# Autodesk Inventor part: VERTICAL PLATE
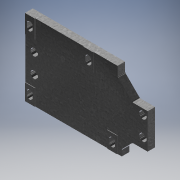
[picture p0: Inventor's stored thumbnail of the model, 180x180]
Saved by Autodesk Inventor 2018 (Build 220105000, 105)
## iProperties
Created: 2004-06
Part Number: VERTICAL PLATE
Document SubType Name: Modeling
Manufacturer: Standard
Standards Organization: Custom
Material: Steel, Mild
Density: 7.86 g/cm^3
Mass: 3865.22 g
Surface Area: 833.818 cm^2
Volume: 491.758 cm^3
Appearance: Steel Galvanized
Author: Autodesk, Inc.
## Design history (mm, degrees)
sketch "Sketch1"
  geometry: L1 (-123.35, 77)-(123.35, 77); L2 (123.35, 77)-(123.35, -77); L3 (123.35, -77)-(-123.35, -77); L4 (-123.35, -77)-(-123.35, 77); 3 further points
  constraints: 8 end point, 2 midpoint, 2 parallel, 1 horizontal, 1 horizontal alignment, 1 perpendicular, 1 vertical alignment
  dimensions: "d0" = 246.7 distance of L1.start L1.end; "d1" = 154 distance of L1.end L2.end
extrude "Extrusion1" new body sketch "Sketch1" distance "d2" = 15; taper "d3" = 0 deg
sketch "Sketch2"
  geometry: L1 (-123.35, 77)-(123.35, 77) reference; L2 (123.35, 77)-(123.35, -77) reference; L3 (62.65, 77)-(62.65, 28.2); L4 (62.65, 28.2)-(123.35, 28.2); L5 (123.35, -77)-(-123.35, -77) reference; L6 (62.65, 58.2)-(92.65, 28.2)
  constraints: 6 end point, 4 point on line, 2 perpendicular
  dimensions: "d4" = 60.7 distance between parallel lines of L2 L3; "d5" = 105.2 distance between parallel lines of L4 L5; "d6" = 45 deg angle of L6 L4; "d7" = 30.7 distance from line of L2 L6.end
extrude "Extrusion2" cut sketch "Sketch2" extent not by distance; stored distance "d8" = 15; taper "d9" = 0 deg
sketch "Sketch3"
  geometry: L1 (123.35, 28.2)-(123.35, -77) reference; L2 (123.35, -42.45)-(92.65, -42.45); L3 (92.65, -42.45)-(71.05, -64.05); L4 (71.05, -64.05)-(71.05, -77); L5 (123.35, -77)-(-123.35, -77) reference; 2 further points
  constraints: 6 end point, 2 perpendicular, 2 point on line, 1 vertical alignment
  dimensions: "d10" = 34.55 distance between parallel lines of L5 L2; "d11" = 45 deg angle of L2 L3; "d41" = 52.3 distance between parallel lines of L1 L4
extrude "Extrusion3" cut sketch "Sketch3" extent not by distance; stored distance "d12" = 15; taper "d13" = 0 deg
fillet "Fillet1" dims "d14" = 6.35
sketch "Sketch4"
  geometry: L1 (-123.35, 77)-(-103.35, 77); L2 (-103.35, 77)-(-103.35, 40); L3 (-103.35, 40)-(-123.35, 40); L4 (-123.35, 40)-(-123.35, 77)
  constraints: 8 end point, 2 parallel, 1 horizontal, 1 perpendicular
  dimensions: "d15" = 37 distance from line of L1.start L3; "d16" = 20 distance of L1.start L1.end
extrude "Extrusion4" join sketch "Sketch4" distance "d17" = 1; taper "d18" = 0 deg
sketch "Sketch5"
  geometry: L1 (-119.35, 55.5)-(-119.35, 61.5); L2 (-107.35, 61.5)-(-107.35, 55.5); L3 (-119.35, 58.5)-(-107.35, 58.5); L4 (-103.35, 77)-(-103.35, 40) reference; L5 (-103.35, 40)-(-123.35, 40) reference; A1 r 6 centre (-113.35, 61.5) between (-107.35, 61.5) and (-119.35, 61.5); A2 r 6 centre (-113.35, 55.5) between (-119.35, 55.5) and (-107.35, 55.5); 3 further points
  constraints: 6 end point, 5 midpoint, 4 point on circle, 4 tangent, 2 centre point, 1 horizontal alignment, 1 parallel, 1 vertical, 1 vertical alignment
  dimensions: "d23" = 12 distance between parallel lines of L2 L1; "d24" = 18 dimension on A2 A1
extrude "Extrusion5" cut sketch "Sketch5" extent not by distance; stored distance "d21" = 1; taper "d22" = 0 deg
workpoint "Work Point3"
pattern_linear "Rectangular Pattern1" dims "d27" = 118
sketch "Sketch6"
  geometry: L1 (-123.35, -77)-(-103.35, -77); L2 (-103.35, -77)-(-103.35, -44.4); L3 (-103.35, -44.4)-(-123.35, -44.4); L4 (-123.35, -44.4)-(-123.35, -77); 1 further point
  constraints: 8 end point, 2 parallel, 1 horizontal, 1 perpendicular, 1 vertical alignment
  dimensions: "d30" = 32.6 distance of L3.end L1.start
extrude "Extrusion6" join sketch "Sketch6" distance "d31" = 1; taper "d32" = 0 deg
sketch "Sketch7"
  geometry: L1 (-119.35, 55.5)-(-119.35, 61.5); L2 (-107.35, 61.5)-(-107.35, 55.5); L3 (-119.35, 58.5)-(-107.35, 58.5); L4 (-103.35, 77)-(-103.35, 40); L5 (-103.35, 40)-(-123.35, 40); A1 r 6 centre (-113.35, 61.5) between (-107.35, 61.5) and (-119.35, 61.5); A2 r 6 centre (-113.35, 55.5) between (-119.35, 55.5) and (-107.35, 55.5); 3 further points
  constraints: 10 end point, 5 midpoint, 4 point on circle, 4 tangent, 2 centre point, 1 horizontal alignment, 1 parallel, 1 vertical, 1 vertical alignment
  dimensions: "d34" = 12 distance between parallel lines of L2 L1; "d33" = 18 dimension on A2 A1
extrude "Extrusion7" cut sketch "Sketch7" extent not by distance; taper "d36" = 0 deg; stored distance "d37" = 1
workpoint "Work Point1"
pattern_linear "Rectangular Pattern2" dims "d40" = 166
hole "Hole1" diameter "d44" = 8.8; stored, may be unused: countersink angle "d48" = 90 deg, drill point angle "d50" = 118 deg; dims "d42" = 18, "d43" = 54.55, "d45" = 6, "d46" = 15, "d47" = 9, "d49" = 8
pattern_linear "Rectangular Pattern3" dims "d53" = 39.13, "d56" = 219.2 (computed from d44)
body "Solid1"
workpoint "Work Point2"
workpoint "Work Point4"
